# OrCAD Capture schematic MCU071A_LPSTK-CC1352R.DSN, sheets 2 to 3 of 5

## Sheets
2 2_Peripherals: size A3
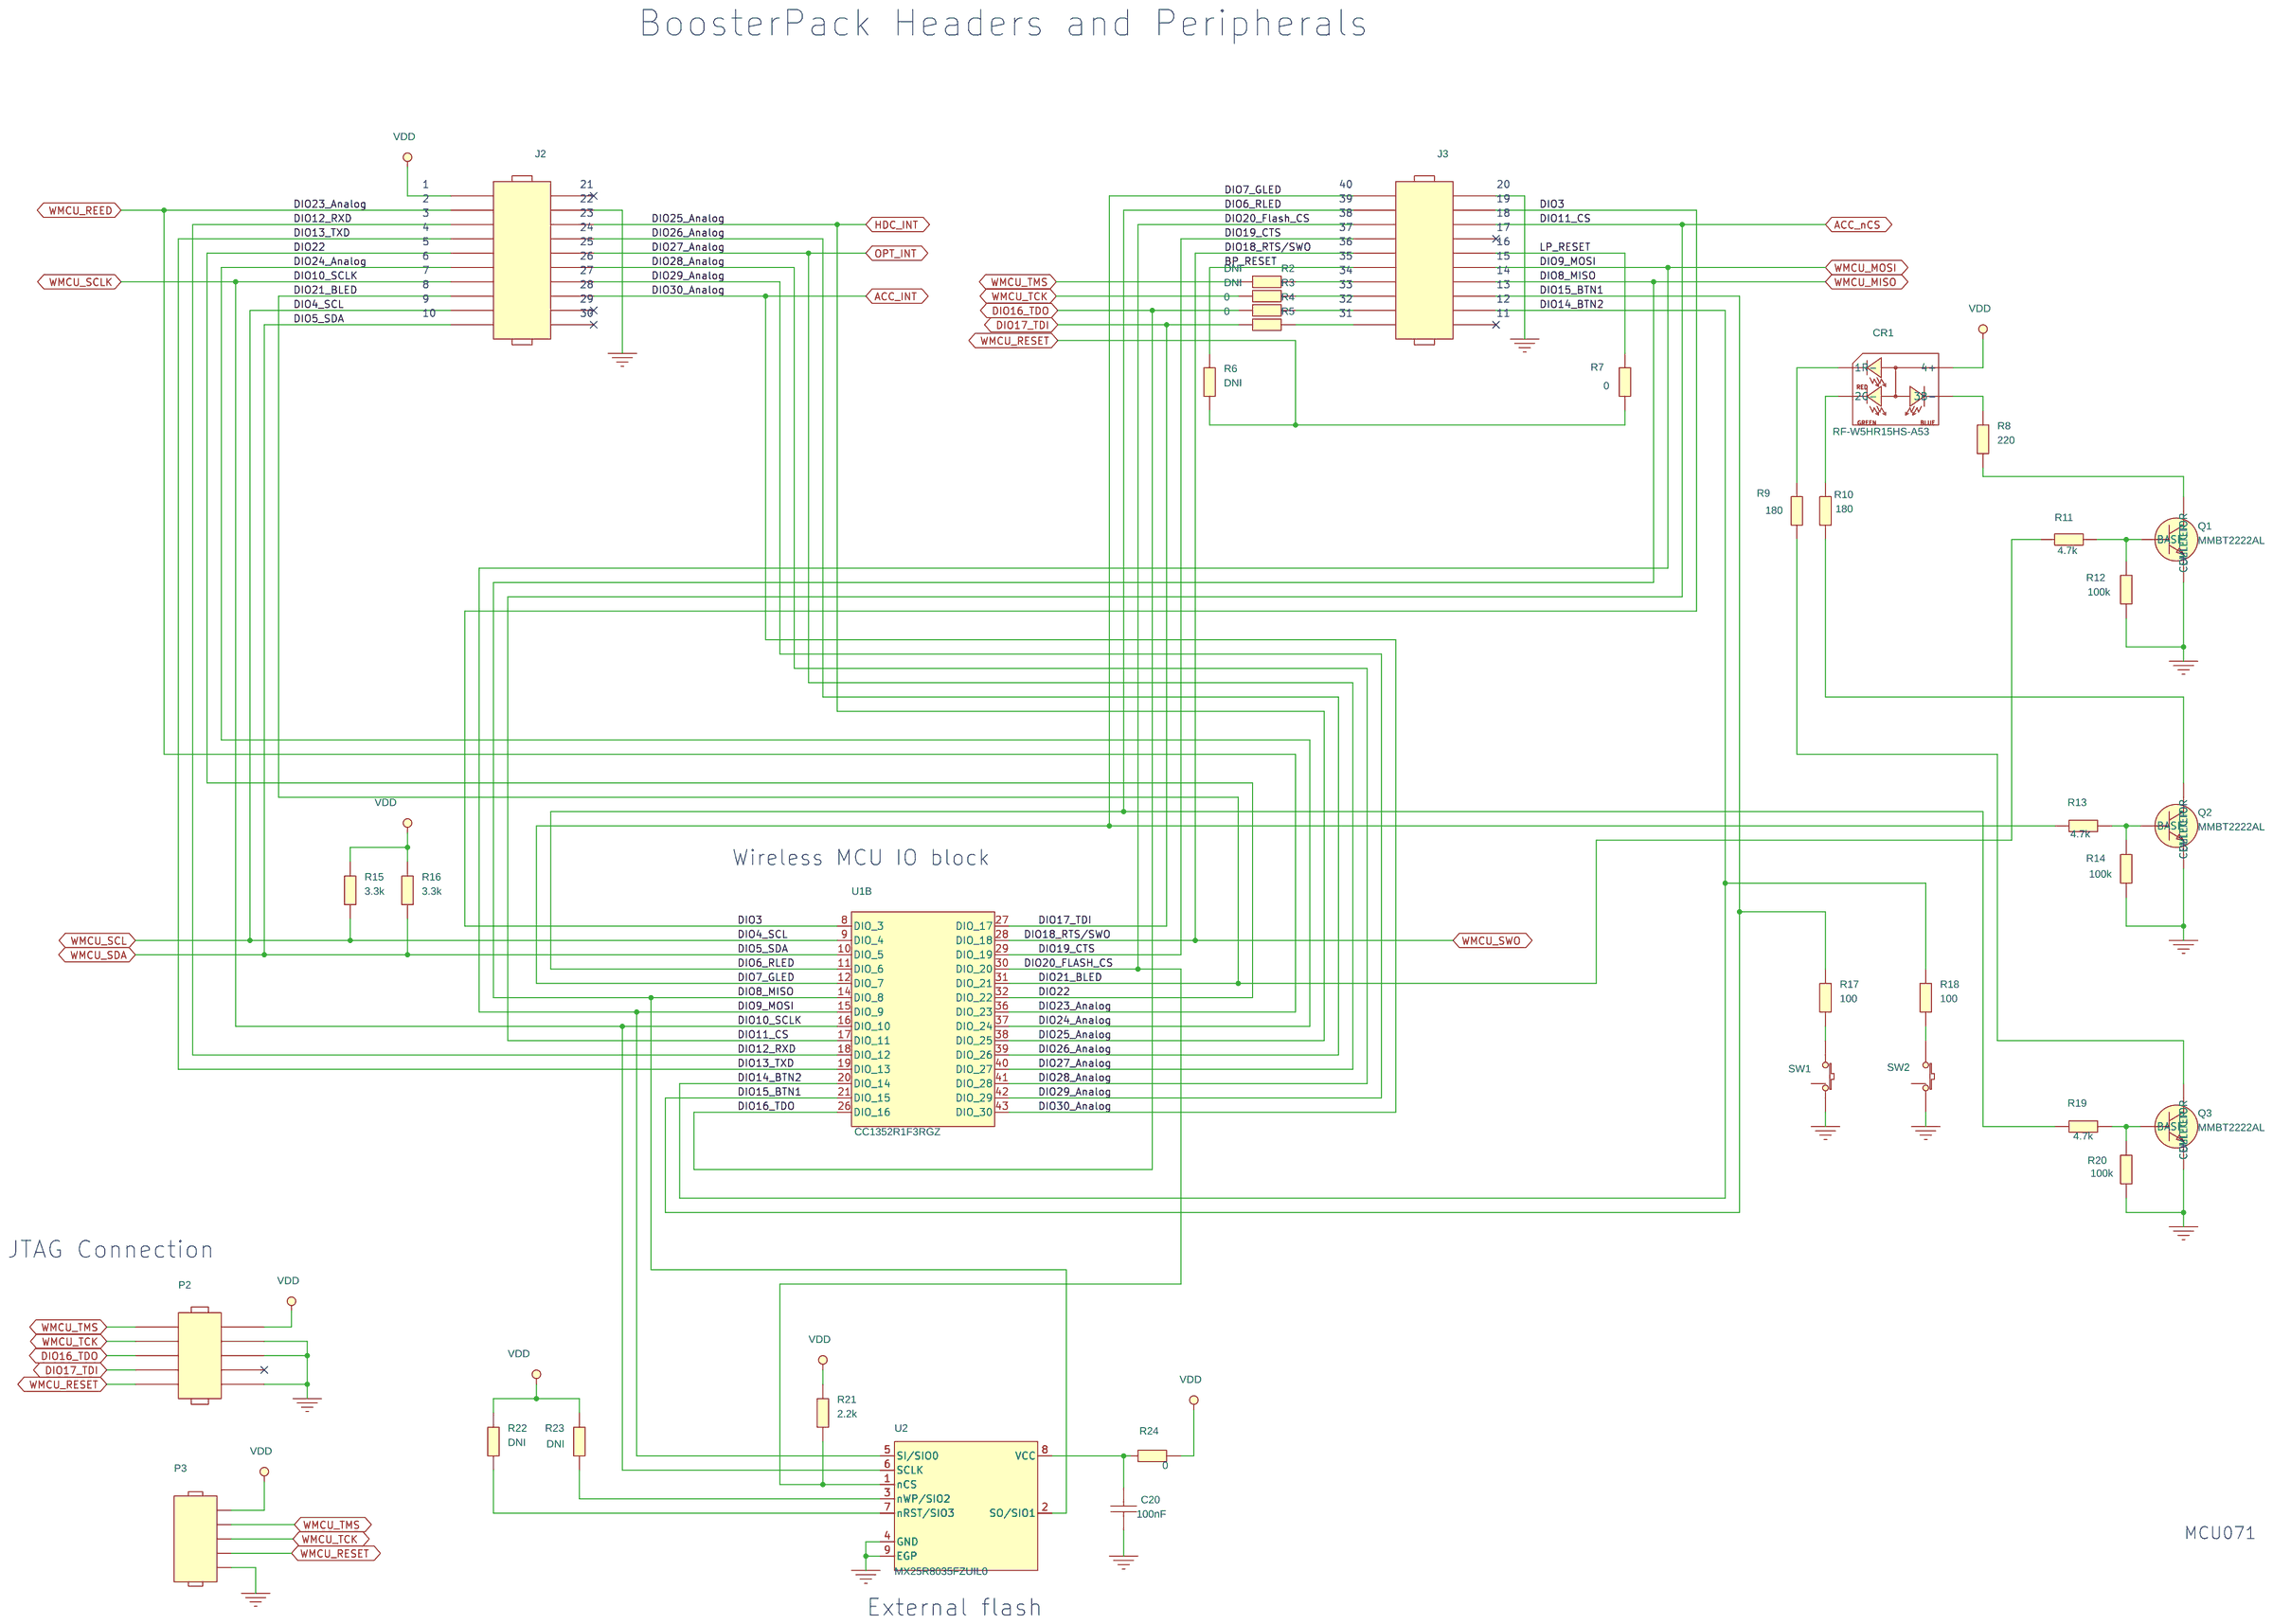
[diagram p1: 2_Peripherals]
3 3_Sensors: size A3; title: LPSTK- CC1352R1
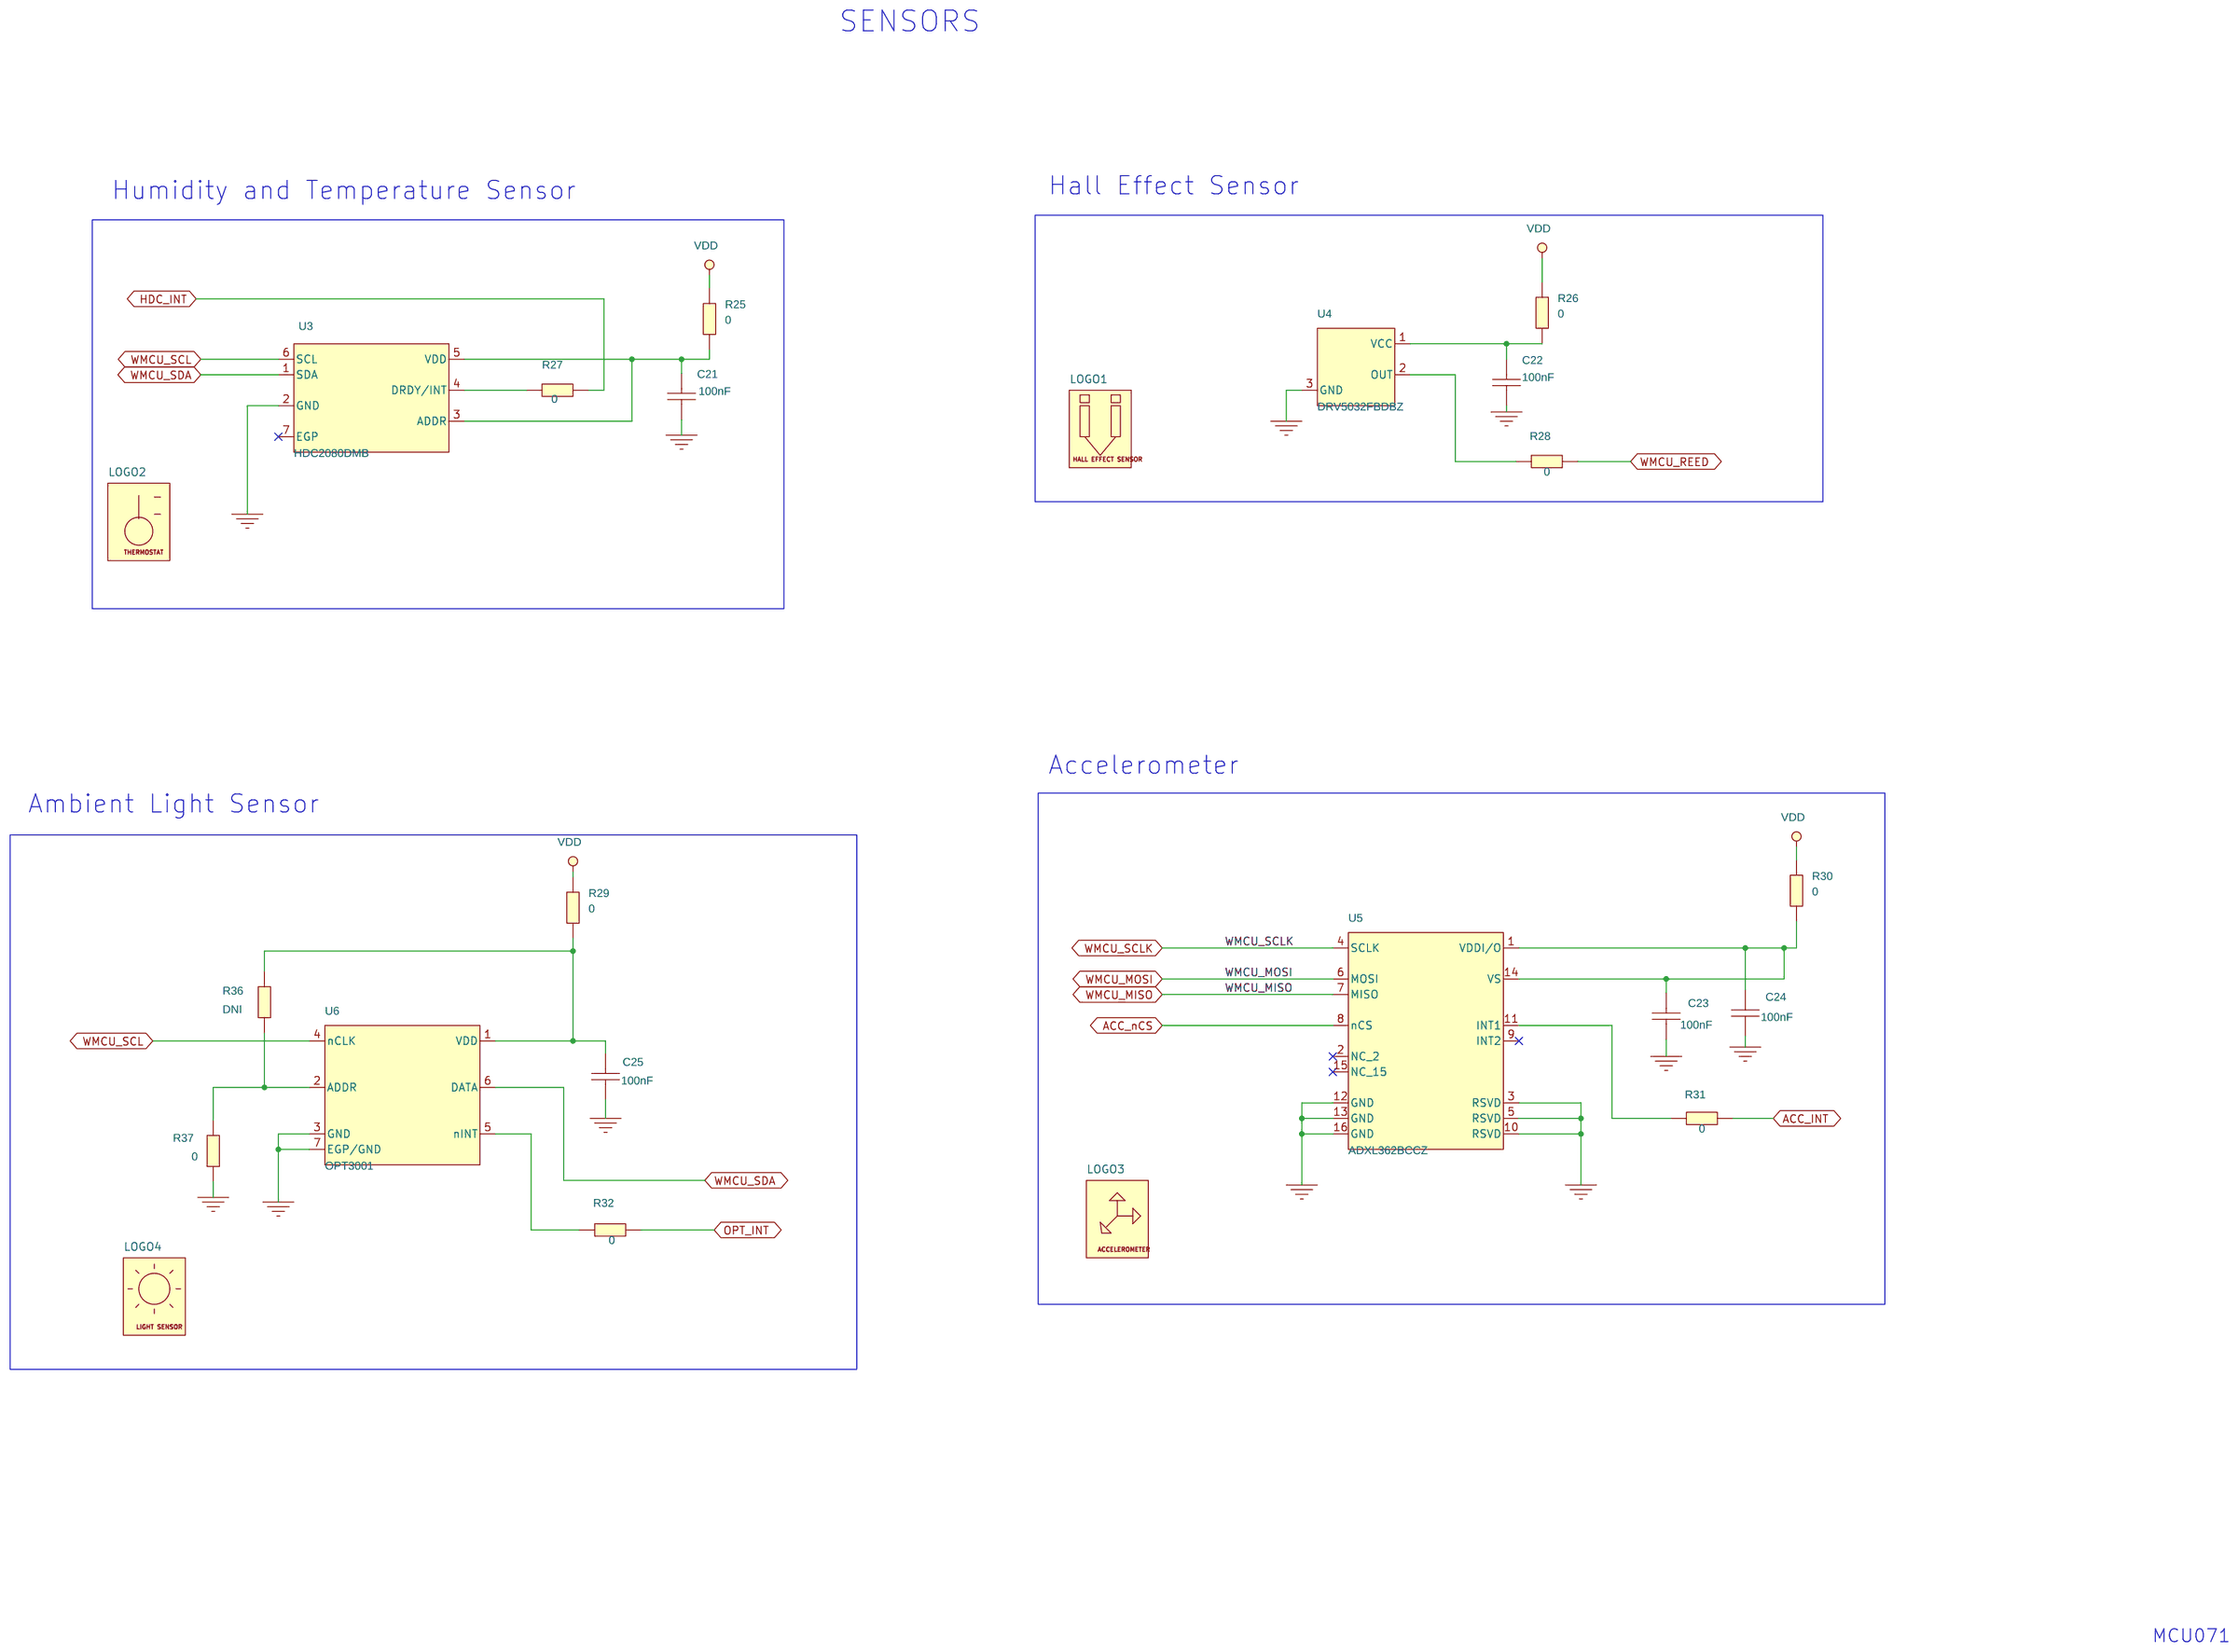
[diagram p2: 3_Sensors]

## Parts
sheet 1_RF
U1  CC1352R1F3RGZ  [QFNFC50P700X700X100-49A2N]  (sections A,B)
sheet 2_Peripherals
C20  100nF  [CAPC1005X60A2N]
CR1  RF-W5HR15HS-A53  [LED_RFW5HR15HSA53_A2N]
J2  313220S1411  [HARWIN_M209761046B]
J3  313220S1411  [HARWIN_M209761046B]
P2  FTSH-105-01-F-DV-K  [SAMTEC_FTSH10501FDVK_A2N]
P3  DNI  [HARWIN_M52040023V0545_A2B]
Q1  MMBT2222AL  [SOT95P237X111-3A2N]
Q2  MMBT2222AL  [SOT95P237X111-3A2N]
Q3  MMBT2222AL  [SOT95P237X111-3A2N]
R2  DNI  [RESC0603X35B2N]
R3  DNI  [RESC0603X35B2N]
R4  0  [RESC0603X35B2N]
R5  0  [RESC0603X35B2N]
R6  DNI  [RESC1005X40B2N]
R7  0  [RESC1005X40A2N]
R8  220  [RESC1005X40B2N]
R9  180  [RESC1005X40B2N]
R10  180  [RESC1005X40B2N]
R11  4.7k  [RESC0603X35B2N]
R12  100k  [RESC0603X35B2N]
R13  4.7k  [RESC0603X35B2N]
R14  100k  [RESC0603X35B2N]
R15  3.3k  [RESC1005X40B2N]
R16  3.3k  [RESC1005X40B2N]
R17  100  [RESC1005X40B2N]
R18  100  [RESC1005X40B2N]
R19  4.7k  [RESC0603X35B2N]
R20  100k  [RESC0603X35B2N]
R21  2.2k  [RESC1005X40B2N]
R22  DNI  [RESC1005X40B2N]
R23  DNI  [RESC1005X40B2N]
R24  0  [RESC0603X35B2N]
SW1  MTA2-WNC  [SW_MTA2CN]
SW2  MTA2-WNC  [SW_MTA2CN]
U2  MX25R8035FZUIL0  [SON50P300X200X60-9B2N]
sheet 3_Sensors
C21  100nF  [CAPC1005X60A2N]
C22  100nF  [CAPC1005X60A2N]
C23  100nF  [CAPC1005X60A2N]
C24  100nF  [CAPC1005X60A2N]
C25  100nF  [CAPC1005X60A2N]
LOGO1  Logo_HALL_EFFECT_SENSOR  [LABEL_HALL_EFFECT_SENSOR_TI]
LOGO2  Logo_THERMOSTAT  [LABEL_THERMOSTAT_TI]
LOGO3  Logo_ACCELEROMETER  [LABEL_ACCELEROMETER_TI]
LOGO4  Logo_LIGHT_SENSOR  [LABEL_LIGHT_SENSOR_TI]
R25  0  [RESC0603X35B2N]
R26  0  [RESC0603X35B2N]
R27  0  [RESC0603X35B2N]
R28  0  [RESC0603X35B2N]
R29  0  [RESC0603X35B2N]
R30  0  [RESC0603X35B2N]
R31  0  [RESC0603X35B2N]
R32  0  [RESC0603X35B2N]
R36  DNI  [RESC0603X35B2N]
R37  0  [RESC0603X35B2N]
U3  HDC2080DMB  [SON100P300X300X80-7B2N]
U4  DRV5032FBDBZ  [SOT95P237X112-3A2N]
U5  ADXL362BCCZ  [LGAFC16S50P300X325X114]
U6  OPT3001  [SON65P200X200X65-7N]

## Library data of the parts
U1 = IC_RF_CC1352_QFN48_V1: IC, CUSTOM, CC1352R1F3RGZ, QFN48-EP, SMD; ALT_SYMBOLS: QFNFC50P700X700X100-49A2L,QFNFC50P700X700X100-49A2M; Additional Datasheet URL: http://www.ti.com/lit/ml/mpqf123f/mpqf123f.pdf; Datasheet URL: http://www.ti.com/lit/ds/symlink/cc1352r.pdf; Exclusive for Customers: TEXAS INSTRUMENTS NORWAY; Mass: N/A; Maximum Operating Temperature: N/A; Minimum Operating Temperature: N/A; Mounting Type: SMD; NOTEfied URL: https://notefied-dynamic-precision.com/NOTEfiedWebInterface/part/show?partNumber=18-33499; Notes: Custom item: preliminary.; PCB Package: QFN48-EP; Packing Size: 250; Packing Type: Missing Info; Part Number: 18-33499; Part Type: IC|DIGITAL|WIRELESS|OTHER; REACH/SVHC Compliance: Missing Info; REACH/SVHC Details: N/A; REACH/SVHC Source: N/A; REACH/SVHC Status: Missing Info; ROHS: Missing Info; Rated Voltage: N/A; Revision: R019; Status: Released; Texas Part Status: Under Review; Type: IC; Vendor: TEXAS INSTRUMENTS; Vendor Part Number: CC1352R1F3RGZT; Vendor Part Status: Preliminary
C20-C25 = CAPACITOR: CAPACITOR, CERAMIC X5R, 100nF, 10V, -10%+/10%, -55DEGC /+85DEGC, 0402, SMD; ALT_SYMBOLS: CAPC1005X60A2L,CAPC1005X60A2M; Additional Datasheet URL: http://www.avx.com/products/ceramic-capacitors/surface-mount/x5r-dielectric/; Budgetary Price: 0.004 EUR; Country of Origin: China,Czech Republic,El Salvador,Japan,Malaysia,United Kingdom; Datasheet URL: http://datasheets.avx.com/cx5r.pdf; Dielectric Type: X5R; Lead Time: 11; Mass: 0.001g; Maximum Operating Temperature: +85DEGC; Maximum Tolerance: +10%; Minimum Operating Temperature: -55DEGC; Minimum Tolerance: -10%; Mounting Type: SMD; NOTEfied URL: https://notefied-dynamic-precision.com/NOTEfiedWebInterface/part/show?partNumber=02-04065; PCB Package: 0402; Packing Size: 10000; Packing Type: Tape & Reel; Part Number: 02-04065; Part Type: Capacitor|CERAMIC|0402|STANDARD; ROHS: Compliant; Rated Voltage: 10V; Revision: R008; Status: Released; Type: Capacitor; Vendor: AVX; Vendor Part Number: 0402ZD104KAT2A; Vendor Part Status: Active
CR1 = LED_RGB_V1_0: OPTO, LED, RGB, 618nm TO 628nm/525nm TO 535nm/460nm TO 470nm, 1.6V TO 2.3V/2.4V TO 3.1V/2.4V TO 3.1V, 0.008A/0.005A/0.003A, 0.046W/0.047W/0.047W, SMD; ALT_SYMBOLS: LED_RFW5HR15HSA53_A2L,LED_RFW5HR15HSA53_A2M; Additional Datasheet URL: N/A; Datasheet URL: http://www.refond.com; Mass: N/A; Maximum Operating Temperature: +85DEGC; Minimum Operating Temperature: -30DEGC; Mounting Type: SMD; NOTEfied URL: https://notefied-dynamic-precision.com/NOTEfiedWebInterface/part/show?partNumber=15-03036; Packing Size: 15000; Packing Type: Tape & Reel; Part Number: 15-03036; Part Type: Opto|LED|OTHER SMD; REACH/SVHC Compliance: Missing Info; REACH/SVHC Details: N/A; REACH/SVHC Source: N/A; REACH/SVHC Status: Missing Info; ROHS: Compliant; Rated Current: 0.008A / 0.005A / 0.003A; Rated Power: 0.046W / 0.047W / 0.047W; Rated Voltage: 1.6V TO 2.3V / 2.4V TO 3.1V / 2.4V TO 3.1V; Revision: R001; Status: Released; Texas Part Status: Under Review; Type: Opto; Vendor: REFOND; Vendor Part Status: Active
J2 J3 = CONN_HEADER_2X10_P: CONNECTOR, HEADER, MALE, STRAIGHT, 2 ROWS, 20 PINS, PITCH 2.54mm, PTH; ALT_SYMBOLS: HARWIN_M209761046C,HARWIN_M209761046A; Additional Datasheet URL: https://cdn.harwin.com/pdfs/M20-976.pdf; Budgetary Price: 0.32175 USD; CLASS: IO; Country of Origin: United States,United Kingdom,Singapore; Datasheet URL: https://cdn.harwin.com/pdfs/C001XX_M20_Series_Connectors.pdf; Lead Time: 7; Mass: 1.056g; Maximum Operating Temperature: +105DEGC; Minimum Operating Temperature: -40DEGC; Mounting Type: PTH; NOTEfied URL: https://notefied-dynamic-precision.com/NOTEfiedWebInterface/part/show?partNumber=06-00136; Number of Positions: 20; Number of Rows: 2; Packing Size: 300; Packing Type: Bulk; Part Number: 06-00136; Part Type: Connector|HEADER|STANDARD; Pitch: 2.54mm; ROHS: Compliant; Rated Current: 3A; Revision: R009; Status: Released; Type: Connector; Vendor: LYCONN; Vendor Part Status: Active
P2 = CONN_HEADER_2X5: CONNECTOR, HEADER, MALE, STRAIGHT, 2 ROWS, 10 PINS, PITCH 1.27mm, SMD; ALT_SYMBOLS: SAMTEC_FTSH10501FDVK_A2L,SAMTEC_FTSH10501FDVK_A2M; Additional Datasheet URL: http://suddendocs.samtec.com/prints/ftsh-1xx-xx-xxx-dv-xxx-xxx-mkt.pdf; Budgetary Price: 1.682 USD; CLASS: IO; Country of Origin: China,Costa Rica,Malaysia,Singapore,United States; Datasheet URL: http://suddendocs.samtec.com/catalog_english/ftsh_smt.pdf; FPLIST: SAMTEC_FTSH10501FDVK_A2N,SAMTEC_FTSH-105-01-F-DV-K-10N; Lead Time: 3; Mass: 0.31701g; Maximum Operating Temperature: +125DEGC; Minimum Operating Temperature: -55DEGC; Mounting Type: SMD; NOTEfied URL: https://notefied-dynamic-precision.com/NOTEfiedWebInterface/part/show?partNumber=06-00166; Number of Positions: 10; Number of Rows: 2; Packing Size: 92; Packing Type: Tube; Part Number: 06-00166; Part Type: Connector|HEADER|STANDARD; Pitch: 1.27mm; REACH/SVHC Compliance: Compliant; REACH/SVHC Details: SVHC List Version Jun 20, 2016; REACH/SVHC Source: Material Declaration; REACH/SVHC Status: Unaffected; ROHS: Compliant; Rated Current: 1.75A; Revision: R017; Status: Released; Texas Part Status: Under Review; Type: Connector; Vendor: SAMTEC; Vendor Part Status: Active
P3 = CONN_HEADER_5_P_S: CONNECTOR, HEADER, MALE, STRAIGHT, 1 ROW, 5 PINS, PITCH 1.27mm, PTH; Additional Datasheet URL: https://cdn.harwin.com/pdfs/M52-040023VXX45.pdf; Budgetary Price: 0.36465 USD; Country of Origin: Taiwan; Datasheet URL: https://cdn.harwin.com/pdfs/C029XX_M50_and_M52_Series_Connectors.pdf; Lead Time: 7; Mass: 0.135g; Maximum Operating Temperature: +105DEGC; Minimum Operating Temperature: -40DEGC; Mounting Type: PTH; NOTEfied URL: https://notefied-dynamic-precision.com/NOTEfiedWebInterface/part/show?partNumber=06-04967; Number of Positions: 5; Number of Rows: 1; Packing Size: 1000; Packing Type: Bulk; Part Number: 06-04967; Part Type: Connector|HEADER|STANDARD; Pitch: 1.27mm; ROHS: Compliant; Rated Current: 1A; Revision: R012; Status: Released; Texas Part Status: Under Review; Type: Connector; Vendor: HARWIN; Vendor Part Number: M52-040023V0545; Vendor Part Status: Active
Q1-Q3 = NPN_BEC: TRANSISTOR, BIPOLAR, NPN, 40V, 0.6A, 0.225W, SOT23-3, SMD; ALT_SYMBOLS: SOT95P237X111-3A2L,SOT95P237X111-3A2M; Additional Datasheet URL: http://www.onsemi.com/pub/Collateral/318-08.PDF; Budgetary Price: 0.0123 USD; Country of Origin: China; Datasheet URL: http://www.onsemi.com/pub/Collateral/MMBT2222LT1-D.PDF; Lead Time: 4; Mass: 0.00802g; Maximum Operating Temperature: +150DEGC; Minimum Operating Temperature: -55DEGC; Mounting Type: SMD; NOTEfied URL: https://notefied-dynamic-precision.com/NOTEfiedWebInterface/part/show?partNumber=16-00819; PCB Package: SOT23-3; Packing Size: 3000; Packing Type: Tape & Reel; Part Number: 16-00819; Part Type: Transistor|BIPOLAR|NPN; ROHS: Compliant; Rated Current: 0.6A; Rated Power: 0.225W; Rated Voltage: 40V; Revision: R023; Status: Released; Type: Transistor; Vendor: ON SEMICONDUCTOR; Vendor Part Number: MMBT2222ALT1G; Vendor Part Status: Active
R2 R3 R36 = RESISTOR: RESISTOR, TBD, 0201, SMD, DNM; ALT_SYMBOLS: RESC0603X35B2L,RESC0603X35B2M; Additional Datasheet URL: N/A; Country of Origin: Missing Info; Datasheet URL: N/A; Maximum Operating Temperature: N/A; Maximum Temperature Coefficient: N/A; Maximum Tolerance: N/A; Minimum Operating Temperature: N/A; Minimum Temperature Coeficient: N/A; Minimum Tolerance: N/A; Mounting Type: SMD; NOTEfied URL: https://notefied-dynamic-precision.com/NOTEfiedWebInterface/part/show?partNumber=01-02470; PCB Package: 0201; Part Number: 01-02470; Part Type: Resistor|0201|STANDARD; ROHS: Compliant; Rated Current: N/A; Rated Power: N/A; Rated Voltage: N/A; Resistance: N/A; Revision: R014; Status: Released; Texas Part Status: Under Review; Type: Resistor; Vendor: MANUFACTURER SELECTION; Vendor Part Number: RESISTOR_TBD_0201_DNM; Vendor Part Status: Active
R4 R5 R24-R32 R37 = RESISTOR: RESISTOR, THICK FILM, 0, 0.05W, 30V, -55DEGC/+155DEGC, 0201, SMD; ALT_SYMBOLS: RESC0603X35B2L,RESC0603X35B2M; Additional Datasheet URL: N/A; Budgetary Price: 0.0243 USD; Country of Origin: Missing Info; Datasheet URL: N/A; Mass: N/A; Maximum Operating Temperature: +155DEGC; Maximum Temperature Coefficient: +100PPM/DEGC; Maximum Tolerance: N/A; Minimum Operating Temperature: -55DEGC; Minimum Temperature Coeficient: -100PPM/DEGC; Minimum Tolerance: N/A; Mounting Type: SMD; NOTEfied URL: https://notefied-dynamic-precision.com/NOTEfiedWebInterface/part/show?partNumber=01-02467; PCB Package: 0201; Packing Size: 5000; Packing Type: Tape & Reel; Part Number: 01-02467; Part Type: Resistor|0201|JUMPER; ROHS: Compliant; Rated Current: N/A; Rated Power: 0.05W; Rated Voltage: 30V; Resistor Type: THICK FILM; Revision: R011; Status: Released; Type: Resistor; Vendor: Yageo; Vendor Part Number: RC0201FR-070RL; Vendor Part Status: Active
R6 R22 R23 = RESISTOR: RESISTOR, TBD, 0402, SMD, DNM; Additional Datasheet URL: N/A; AutoDoc File: https://notefied-dynamic-precision.com/DB/Apps/Desktop/Item/Object.aspx?id=113312; BU Name: TEXAS INSTRUMENTS NORWAY; Budget Currency: N/A; Budget Price: N/A; Country of Origin: Missing Info; Datasheet URL: N/A; Datasheet URL 1: N/A; Datasheet URL 2: N/A; Esd Level: N/A; Exclusive for Customers: TEXAS INSTRUMENTS NORWAY; LifeCycle Status: ACTIVE; MPN: DNM; MPN Status: ACTIVE; MSL: N/A; MTBF: N/A; MTBF Standard: N/A; Manufacturer: DO NOT MOUNT; Max Oper Temp: N/A; Max TC: N/A; Max Tol: N/A; Maximum Operating Temperature: N/A; Maximum Temperature Coefficient: N/A; Maximum Tolerance: N/A; Min Oper Temp: N/A; Min TC: N/A; Min Tol: N/A; Minimum Operating Temperature: N/A; Minimum Temperature Coeficient: N/A; Minimum Tolerance: N/A; Mounting Type: SMD; NOTE Status: PREFERRED; NOTEfied URL: https://notefied-dynamic-precision.com/NOTEfiedWebInterface/part/show?partNumber=01-22339; Notes: Standard item: Duplicate Reason: custom footprint for TEXAS INSTRUMENTS NORWAY.; Old Footprint: RESC1005X40N,0402; PCB Package: 0402; Part Number: 01-22339; Part Type: Resistor|0402|STANDARD; ROHS: Compliant; Rated Current: N/A; Rated Power: N/A; Rated Voltage: N/A; Resistance: N/A; Resistor Type: THICK FILM; Revision: R012; RoHS Status: MISSING_INFO; Rtd Current: N/A; Rtd Power: N/A; Rtd Voltage: N/A; Status: Released; Texas Part Status: Under Review; Type: Resistor; Vendor: MANUFACTURER SELECTION; Vendor Part Number: RESISTOR_TBD_0402_DNM; Vendor Part Status: Active; WEIGHT: N/A
R7 = RESISTOR: RESISTOR, THICK FILM, 0, 0.063W, 50V, -55DEGC/+155DEGC, 0402, SMD; ALT_SYMBOLS: RESC1005X40A2L,RESC1005X40A2M; Additional Datasheet URL: N/A; Budgetary Price: 0.00244 USD; Country of Origin: Missing Info; Datasheet URL: N/A; Mass: N/A; Maximum Operating Temperature: +155DEGC; Maximum Temperature Coefficient: +200PPM/DEGC; Maximum Tolerance: N/A; Minimum Operating Temperature: -55DEGC; Minimum Temperature Coeficient: -200PPM/DEGC; Minimum Tolerance: N/A; Mounting Type: SMD; NOTEfied URL: https://notefied-dynamic-precision.com/NOTEfiedWebInterface/part/show?partNumber=01-11587; PCB Package: 0402; Packing Size: 10000; Packing Type: Tape & Reel; Part Number: 01-11587; Part Type: Resistor|0402|JUMPER; ROHS: Compliant; Rated Current: N/A; Rated Power: 0.063W; Rated Voltage: 50V; Resistor Type: THICK FILM; Revision: R014; Status: Released; Type: Resistor; Vendor: Yageo; Vendor Part Number: RC0402JR-070RL; Vendor Part Status: Active
R8 = RESISTOR: RESISTOR, THICK FILM, 220, -5%/+5%, 0.063W, 50V, -55DEGC/+155DEGC, 0402, SMD; Additional Datasheet URL: N/A; AutoDoc File: https://notefied-dynamic-precision.com/DB/Apps/Desktop/Item/Object.aspx?id=113319; BU Name: TEXAS INSTRUMENTS NORWAY; Budget Currency: EUR; Budget Price: 0.014; Budgetary Price: 0.014 EUR; Client Status: UNDER_REVIEW; Country of Origin: Israel; Datasheet URL: http://www.vishay.com/docs/20035/dcrcwe3.pdf; Datasheet URL 1: http://www.vishay.com/docs/20035/dcrcwe3.pdf; Datasheet URL 2: N/A; Definied Quality: INDUSTRIAL; Esd Level: N/A; Exclusive for Customers: TEXAS INSTRUMENTS NORWAY; Lead Time: 18; LifeCycle Status: ACTIVE; MPN: RESISTOR_0402_220_+/-5%_50V_0.063W_M_+/-200ppm; MPN Status: ACTIVE; MSL: N/A; MTBF: N/A; MTBF Standard: N/A; Manufacturer: MANUFACTURER SELECTION; Mass: 0.00065g; Max Oper Temp: +155DEGC; Max TC: +200PPM/DEGC; Max Tol: +5%; Maximum Operating Temperature: +155DEGC; Maximum Temperature Coefficient: +200PPM/DEGC; Maximum Tolerance: +5%; Min Oper Temp: -55DEGC; Min TC: -200PPM/DEGC; Min Tol: -5%; Minimum Operating Temperature: -55DEGC; Minimum Temperature Coeficient: -200PPM/DEGC; Minimum Tolerance: -5%; Mounting Type: SMD; NOTE Status: PREFERRED; NOTEfied URL: https://notefied-dynamic-precision.com/NOTEfiedWebInterface/part/show?partNumber=01-22346; Notes: Standard item: Duplicate Reason: custom footprint for TEXAS INSTRUMENTS NORWAY.; Old Footprint: RESC1005X40N; PCB Package: 0402; Packing Size: 10000; Packing Type: Tape & Reel; Part Number: 01-22346; Part Type: Resistor|0402|STANDARD; REACH/SVHC Compliance: Compliant; REACH/SVHC Details: SVHC List Version Jun 20, 2016; REACH/SVHC Source: Material Declaration; REACH/SVHC Status: Unaffected; REACH/SVHC_COMPLIANCE: COMPLIANT; REACH/SVHC_DETAILS: SVHC LIST VERSION Jun 20, 2016; REACH/SVHC_SOURCE: MATERIAL DECLARATION; REACH/SVHC_STATUS: UNAFFECTED; ROHS: Exempt; Rated Current: N/A; Rated Power: 0.063W; Rated Voltage: 50V; Resistor Type: THICK FILM; Revision: R013; RoHS Status: ROHS_COMPLIANT_WITH_EXEMPTION; Rtd Current: N/A; Rtd Power: 0.063W; Rtd Voltage: 50V; Status: Released; Texas Part Status: Under Review; Type: Resistor; Vendor: VISHAY; Vendor Part Number: CRCW0402220RJNED; Vendor Part Status: Active; WEIGHT: 0.00065g
R9 R10 = RESISTOR: RESISTOR, THICK FILM, 180, -5%/+5%, 0.063W, 50V, -55DEGC/+155DEGC, 0402, SMD; Additional Datasheet URL: N/A; AutoDoc File: https://notefied-dynamic-precision.com/DB/Apps/Desktop/Item/Object.aspx?id=113318; BU Name: TEXAS INSTRUMENTS NORWAY; Budget Currency: EUR; Budget Price: 0.014; Budgetary Price: 0.014 EUR; Client Status: UNDER_REVIEW; Country of Origin: Missing Info; Datasheet URL: http://www.vishay.com/docs/20035/dcrcwe3.pdf; Datasheet URL 1: http://www.vishay.com/docs/20035/dcrcwe3.pdf; Datasheet URL 2: N/A; Definied Quality: INDUSTRIAL; Esd Level: N/A; Exclusive for Customers: TEXAS INSTRUMENTS NORWAY; Lead Time: 18; LifeCycle Status: ACTIVE; MPN: RESISTOR_0402_180_+/-5%_50V_0.063W_M_+/-200ppm; MPN Status: ACTIVE; MSL: N/A; MTBF: N/A; MTBF Standard: N/A; Manufacturer: MANUFACTURER SELECTION; Mass: 0.00065g; Max Oper Temp: +155DEGC; Max TC: +200PPM/DEGC; Max Tol: +5%; Maximum Operating Temperature: +155DEGC; Maximum Temperature Coefficient: +200PPM/DEGC; Maximum Tolerance: +5%; Min Oper Temp: -55DEGC; Min TC: -200PPM/DEGC; Min Tol: -5%; Minimum Operating Temperature: -55DEGC; Minimum Temperature Coeficient: -200PPM/DEGC; Minimum Tolerance: -5%; Mounting Type: SMD; NOTE Status: PREFERRED; NOTEfied URL: https://notefied-dynamic-precision.com/NOTEfiedWebInterface/part/show?partNumber=01-22345; Notes: Standard item: Duplicate Reason: custom footprint for TEXAS INSTRUMENTS NORWAY.; Old Footprint: RESC1005X40N; PCB Package: 0402; Packing Size: 10000; Packing Type: Tape & Reel; Part Number: 01-22345; Part Type: Resistor|0402|STANDARD; REACH/SVHC Compliance: Compliant; REACH/SVHC Details: SVHC List Version Jun 20, 2016; REACH/SVHC Source: Material Declaration; REACH/SVHC Status: Unaffected; REACH/SVHC_COMPLIANCE: COMPLIANT; REACH/SVHC_DETAILS: SVHC LIST VERSION Jun 20, 2016; REACH/SVHC_SOURCE: MATERIAL DECLARATION; REACH/SVHC_STATUS: UNAFFECTED; ROHS: Exempt; Rated Current: N/A; Rated Power: 0.063W; Rated Voltage: 50V; Resistor Type: THICK FILM; Revision: R013; RoHS Status: ROHS_COMPLIANT_WITH_EXEMPTION; Rtd Current: N/A; Rtd Power: 0.063W; Rtd Voltage: 50V; Status: Released; Texas Part Status: Under Review; Type: Resistor; Vendor: VISHAY; Vendor Part Number: CRCW0402180RJNED; Vendor Part Status: Active; WEIGHT: 0.00065g
R11 R13 R19 = RESISTOR: RESISTOR, THICK FILM, 4.7k, -5%/+5%, 0.05W, 30V, -55DEGC/+155DEGC, 0201, SMD; ALT_SYMBOLS: RESC0603X35B2L,RESC0603X35B2M; Additional Datasheet URL: N/A; Budgetary Price: 0.0041 USD; Country of Origin: Taiwan; Datasheet URL: http://www.vishay.com/docs/20052/crcw0201e3.pdf; Lead Time: 7; Mass: 0.00017g; Maximum Operating Temperature: +155DEGC; Maximum Temperature Coefficient: +200PPM/DEGC; Maximum Tolerance: +5%; Minimum Operating Temperature: -55DEGC; Minimum Temperature Coeficient: -200PPM/DEGC; Minimum Tolerance: -5%; Mounting Type: SMD; NOTEfied URL: https://notefied-dynamic-precision.com/NOTEfiedWebInterface/part/show?partNumber=01-04188; PCB Package: 0201; Packing Size: 10000; Packing Type: Tape & Reel; Part Number: 01-04188; Part Type: Resistor|0201|STANDARD; ROHS: Exempt; Rated Current: N/A; Rated Power: 0.05W; Rated Voltage: 30V; Resistor Type: THICK FILM; Revision: R005; Status: Released; Type: Resistor; Vendor: VISHAY; Vendor Part Number: CRCW02014K70JNED; Vendor Part Status: Active
R12 R14 R20 = RESISTOR: RESISTOR, THICK FILM, 100k, -5%/+5%, 0.05W, 25V, -55DEGC/+125DEGC, 0201, SMD; ALT_SYMBOLS: RESC0603X35B2L,RESC0603X35B2M; Additional Datasheet URL: N/A; Budgetary Price: 0.00218 USD; Country of Origin: China,Japan,Taiwan; Datasheet URL: https://www.seielect.com/Catalog/SEI-RMCF_RMCP.pdf; Lead Time: 22; Mass: 0.0001509g; Maximum Operating Temperature: +125DEGC; Maximum Temperature Coefficient: +200PPM/DEGC; Maximum Tolerance: +5%; Minimum Operating Temperature: -55DEGC; Minimum Temperature Coeficient: -200PPM/DEGC; Minimum Tolerance: -5%; Mounting Type: SMD; NOTEfied URL: https://notefied-dynamic-precision.com/NOTEfiedWebInterface/part/show?partNumber=01-00530; PCB Package: 0201; Packing Size: 10000; Packing Type: Tape & Reel; Part Number: 01-00530; Part Type: Resistor|0201|STANDARD; ROHS: Exempt; Rated Current: N/A; Rated Power: 0.05W; Rated Voltage: 25V; Resistor Type: THICK FILM; Revision: R007; Status: Released; Type: Resistor; Vendor: SEI STACKPOLE; Vendor Part Number: RMCF0201JT100K; Vendor Part Status: Active
R15 R16 = RESISTOR: RESISTOR, THICK FILM, 3.3k, -5%/+5%, 0.063W, 50V, -55DEGC/+155DEGC, 0402, SMD; Additional Datasheet URL: N/A; AutoDoc File: https://notefied-dynamic-precision.com/DB/Apps/Desktop/Item/Object.aspx?id=114561; BU Name: TEXAS INSTRUMENTS NORWAY; Budget Currency: EUR; Budget Price: 0.014; Budgetary Price: 0.014 EUR; Client Status: UNDER_REVIEW; Country of Origin: Israel; Datasheet URL: http://www.vishay.com/docs/20035/dcrcwe3.pdf; Datasheet URL 1: http://www.vishay.com/docs/20035/dcrcwe3.pdf; Datasheet URL 2: N/A; Definied Quality: INDUSTRIAL; Esd Level: N/A; Exclusive for Customers: TEXAS INSTRUMENTS NORWAY; Lead Time: 18; LifeCycle Status: ACTIVE; MPN: RESISTOR_0402_3.3k_+/-5%_50V_0.063W_M_+/-200ppm; MPN Status: ACTIVE; MSL: N/A; MTBF: N/A; MTBF Standard: N/A; Manufacturer: MANUFACTURER SELECTION; Mass: 0.00065g; Max Oper Temp: +155DEGC; Max TC: +200PPM/DEGC; Max Tol: +5%; Maximum Operating Temperature: +155DEGC; Maximum Temperature Coefficient: +200PPM/DEGC; Maximum Tolerance: +5%; Min Oper Temp: -55DEGC; Min TC: -200PPM/DEGC; Min Tol: -5%; Minimum Operating Temperature: -55DEGC; Minimum Temperature Coeficient: -200PPM/DEGC; Minimum Tolerance: -5%; Mounting Type: SMD; NOTE Status: PREFERRED; NOTEfied URL: https://notefied-dynamic-precision.com/NOTEfiedWebInterface/part/show?partNumber=01-22488; Notes: Standard item: Duplicate Reason: custom footprint for TEXAS INSTRUMENTS NORWAY.; Old Footprint: RESC1005X40N; PCB Package: 0402; Packing Size: 10000; Packing Type: Tape & Reel; Part Number: 01-22488; Part Type: Resistor|0402|STANDARD; REACH/SVHC Compliance: Compliant; REACH/SVHC Details: SVHC List Version Jun 20, 2016; REACH/SVHC Source: Material Declaration; REACH/SVHC Status: Unaffected; REACH/SVHC_COMPLIANCE: COMPLIANT; REACH/SVHC_DETAILS: SVHC LIST VERSION Jun 20, 2016; REACH/SVHC_SOURCE: MATERIAL DECLARATION; REACH/SVHC_STATUS: UNAFFECTED; ROHS: Exempt; Rated Current: N/A; Rated Power: 0.063W; Rated Voltage: 50V; Resistor Type: THICK FILM; Revision: R013; RoHS Status: ROHS_COMPLIANT; Rtd Current: N/A; Rtd Power: 0.063W; Rtd Voltage: 50V; Status: Released; Texas Part Status: Under Review; Type: Resistor; Vendor: VISHAY; Vendor Part Number: CRCW04023K30JNED; Vendor Part Status: Active; WEIGHT: 0.00065g
R17 R18 = RESISTOR: RESISTOR, THICK FILM, 100, -5%/+5%, 0.063W, 50V, -55DEGC/+155DEGC, 0402, SMD; Additional Datasheet URL: N/A; AutoDoc File: https://notefied-dynamic-precision.com/DB/Apps/Desktop/Item/Object.aspx?id=114555; BU Name: TEXAS INSTRUMENTS NORWAY; Budget Currency: USD; Budget Price: 0.0014; Budgetary Price: 0.0014 USD; Client Status: UNDER_REVIEW; Country of Origin: United States; Datasheet URL: http://www.vishay.com/docs/20035/dcrcwe3.pdf; Datasheet URL 1: http://www.vishay.com/docs/20035/dcrcwe3.pdf; Datasheet URL 2: N/A; Definied Quality: INDUSTRIAL; Esd Level: N/A; Exclusive for Customers: TEXAS INSTRUMENTS NORWAY; Lead Time: 16; LifeCycle Status: ACTIVE; MPN: RESISTOR_0402_100_+/-5%_50V_0.063W_M_+/-200ppm; MPN Status: ACTIVE; MSL: N/A; MTBF: N/A; MTBF Standard: N/A; Manufacturer: MANUFACTURER SELECTION; Mass: 0.00065g; Max Oper Temp: +155DEGC; Max TC: +200PPM/DEGC; Max Tol: +5%; Maximum Operating Temperature: +155DEGC; Maximum Temperature Coefficient: +200PPM/DEGC; Maximum Tolerance: +5%; Min Oper Temp: -55DEGC; Min TC: -200PPM/DEGC; Min Tol: -5%; Minimum Operating Temperature: -55DEGC; Minimum Temperature Coeficient: -200PPM/DEGC; Minimum Tolerance: -5%; Mounting Type: SMD; NOTE Status: PREFERRED; NOTEfied URL: https://notefied-dynamic-precision.com/NOTEfiedWebInterface/part/show?partNumber=01-22482; Notes: Standard item: Duplicate Reason: custom footprint for TEXAS INSTRUMENTS NORWAY.; Old Footprint: RESC1005X40N; PCB Package: 0402; Packing Size: 10000; Packing Type: Tape & Reel; Part Number: 01-22482; Part Type: Resistor|0402|STANDARD; REACH/SVHC Compliance: Compliant; REACH/SVHC Details: SVHC List Version Jun 20, 2016; REACH/SVHC Source: Material Declaration; REACH/SVHC Status: Unaffected; REACH/SVHC_COMPLIANCE: COMPLIANT; REACH/SVHC_DETAILS: SVHC LIST VERSION Jun 20, 2016; REACH/SVHC_SOURCE: MATERIAL DECLARATION; REACH/SVHC_STATUS: UNAFFECTED; ROHS: Exempt; Rated Current: N/A; Rated Power: 0.063W; Rated Voltage: 50V; Resistor Type: THICK FILM; Revision: R016; RoHS Status: ROHS_COMPLIANT; Rtd Current: N/A; Rtd Power: 0.063W; Rtd Voltage: 50V; Status: Released; Texas Part Status: Under Review; Type: Resistor; Vendor: VISHAY; Vendor Part Number: CRCW0402100RJNED; Vendor Part Status: Active; WEIGHT: 0.00065g
R21 = RESISTOR: RESISTOR, THICK FILM, 2.2k, -5%/+5%, 0.063W, 50V, -55DEGC/+155DEGC, 0402, SMD; Additional Datasheet URL: N/A; AutoDoc File: https://notefied-dynamic-precision.com/DB/Apps/Desktop/Item/Object.aspx?id=114560; BU Name: TEXAS INSTRUMENTS NORWAY; Budget Currency: EUR; Budget Price: 0.014; Budgetary Price: 0.014 EUR; Client Status: UNDER_REVIEW; Country of Origin: Israel; Datasheet URL: http://www.vishay.com/docs/20035/dcrcwe3.pdf; Datasheet URL 1: http://www.vishay.com/docs/20035/dcrcwe3.pdf; Datasheet URL 2: N/A; Definied Quality: INDUSTRIAL; Esd Level: N/A; Exclusive for Customers: TEXAS INSTRUMENTS NORWAY; Lead Time: 18; LifeCycle Status: ACTIVE; MPN: RESISTOR_0402_2.2k_+/-5%_50V_0.063W_M_+/-200ppm; MPN Status: ACTIVE; MSL: N/A; MTBF: N/A; MTBF Standard: N/A; Manufacturer: MANUFACTURER SELECTION; Mass: 0.00065g; Max Oper Temp: +155DEGC; Max TC: +200PPM/DEGC; Max Tol: +5%; Maximum Operating Temperature: +155DEGC; Maximum Temperature Coefficient: +200PPM/DEGC; Maximum Tolerance: +5%; Min Oper Temp: -55DEGC; Min TC: -200PPM/DEGC; Min Tol: -5%; Minimum Operating Temperature: -55DEGC; Minimum Temperature Coeficient: -200PPM/DEGC; Minimum Tolerance: -5%; Mounting Type: SMD; NOTE Status: PREFERRED; NOTEfied URL: https://notefied-dynamic-precision.com/NOTEfiedWebInterface/part/show?partNumber=01-22487; Notes: Standard item: Duplicate Reason: custom footprint for TEXAS INSTRUMENTS NORWAY.; Old Footprint: RESC1005X40N; PCB Package: 0402; Packing Size: 10000; Packing Type: Tape & Reel; Part Number: 01-22487; Part Type: Resistor|0402|STANDARD; REACH/SVHC Compliance: Compliant; REACH/SVHC Details: SVHC List Version Jun 20, 2016; REACH/SVHC Source: Material Declaration; REACH/SVHC Status: Unaffected; REACH/SVHC_COMPLIANCE: COMPLIANT; REACH/SVHC_DETAILS: SVHC LIST VERSION Jun 20, 2016; REACH/SVHC_SOURCE: MATERIAL DECLARATION; REACH/SVHC_STATUS: UNAFFECTED; ROHS: Exempt; Rated Current: N/A; Rated Power: 0.063W; Rated Voltage: 50V; Resistor Type: THICK FILM; Revision: R013; RoHS Status: ROHS_COMPLIANT; Rtd Current: N/A; Rtd Power: 0.063W; Rtd Voltage: 50V; Status: Released; Texas Part Status: Under Review; Type: Resistor; Vendor: VISHAY; Vendor Part Number: CRCW04022K20JNED; Vendor Part Status: Active; WEIGHT: 0.00065g
SW1 SW2 = SWITCH_1: SWITCH, TACT, RIGHT ANGLE, SPST-NO, 0.05A@12VDC, SMD; Additional Datasheet URL: http://www.dip.com.tw/en/en-product-information/en-switch004/item/2438-mta2; Country of Origin: China,Vietnam; Datasheet URL: http://www.dip.com.tw/en/en-product-information/en-switch004/item/download/2476_096cc44e506e326f4ba9017f6b2ca31d; Mass: N/A; Maximum Operating Temperature: +80DEGC; Minimum Operating Temperature: -30DEGC; Mounting Type: SMD; NOTEfied URL: https://notefied-dynamic-precision.com/NOTEfiedWebInterface/part/show?partNumber=08-00142; Packing Size: 3000; Packing Type: Tape & Reel; Part Number: 08-00142; Part Type: Switch|TACTILE; REACH/SVHC Compliance: Compliant; REACH/SVHC Details: SVHC List Version Dec 17, 2015; REACH/SVHC Source: REACH Declaration; REACH/SVHC Status: Unaffected; ROHS: Compliant; Rated Current: 0.05A; Rated Voltage: 12VDC; Revision: R012; Status: Released; Texas Part Status: Under Review; Type: Switch; Vendor: DIPTRONICS; Vendor Part Number: MTA2-WNC-V-T/R; Vendor Part Status: Active
U2 = IC_FLASH_MX25R8035F_USON8: IC, MEMORY, FLASH, SERIAL, 8Mbit, 1.65V TO 3.6V, USON8, SMD; ALT_SYMBOLS: SON50P300X200X60-9B2L,SON50P300X200X60-9B2M; Additional Datasheet URL: http://www.macronix.com/en-us/products/NOR-Flash/Serial-NOR-Flash/Pages/spec.aspx?p=MX25R8035F&m=Serial%20NOR%20Flash&n=PM2164; AutoDoc File: http://notefied-dynamic-precision.com/DB/Apps/Desktop/Item/Object.aspx?id=104624; Budgetary Price: 0.8598 USD; Country of Origin: Taiwan; Datasheet URL: http://www.macronix.com/Lists/Datasheet/Attachments/7461/MX25R8035F,%20Wide%20Range,%208Mb,%20v1.6.pdf; Datasheet URL 1: N/A; Datasheet URL 2: http://www.macronix.com/Lists/DataSheet/Attachments/2570/MX25R8035F,%20Wide%20Range,%208Mb,%20v0.04.pdf; FPLIST: SON50P300X200X60-9B2N,SON50P300X200X60-9B2L,SON50P300X200X60-9B2M; MPN Status: ACTIVE; Manufacturer: MACRONIX; Mass: N/A; Max Oper Temp: +85DEGC; Maximum Operating Temperature: +85DEGC; Min Oper Temp: -40DEGC; Minimum Operating Temperature: -40DEGC; Mounting Type: SMD; NOTE Status: PREFERRED; NOTEfied URL: https://notefied-dynamic-precision.com/NOTEfiedWebInterface/part/show?partNumber=18-31726; PCB Package: uSON8; Packing Size: 100; Packing Type: Tube; Part Number: 18-31726; Part Type: IC|MEMORY|FLASH|OTHER; REACH/SVHC Compliance: Compliant; REACH/SVHC Details: N/A; REACH/SVHC Source: REACH Declaration & Material Declaration; REACH/SVHC Status: Unaffected; ROHS: Compliant; Rated Voltage: 1.65V TO 3.6V; Revision: R013; RoHS Status: ROHS_COMPLIANT; Rtd Voltage: 1.65V TO 3.6V; Status: Released; Texas Part Status: Under Review; Type: IC; Vendor: MACRONIX; Vendor Part Status: Active
LOGO1 = LABEL_HALL_EFFECT_SENSOR: NON COMPONENT, LOGO, CUSTOM, HALL EFFECT SENSOR; Additional Datasheet URL: N/A; Datasheet URL: N/A; Exclusive for Customers: TEXAS INSTRUMENTS NORWAY; Maximum Operating Temperature: N/A; Minimum Operating Temperature: N/A; Mounting Type: Not Apply; NOTEfied URL: https://notefied-dynamic-precision.com/NOTEfiedWebInterface/part/show?partNumber=19-01166; Notes: Custom Item; Part Number: 19-01166; Part Type: Non Component|LABEL; REACH/SVHC Compliance: Missing Info; REACH/SVHC Details: N/A; REACH/SVHC Source: N/A; REACH/SVHC Status: Missing Info; ROHS: Not Applicable; Revision: R001; Status: Released; Texas Part Status: Under Review; Type: Non Component; Vendor: TEXAS INSTRUMENTS; Vendor Part Status: Active
LOGO2 = LABEL_THERMOSTAT: NON COMPONENT, LOGO, CUSTOM, THERMOSTAT; Additional Datasheet URL: N/A; Datasheet URL: N/A; Exclusive for Customers: TEXAS INSTRUMENTS NORWAY; Maximum Operating Temperature: N/A; Minimum Operating Temperature: N/A; Mounting Type: Not Apply; NOTEfied URL: https://notefied-dynamic-precision.com/NOTEfiedWebInterface/part/show?partNumber=19-01167; Notes: Custom Item; Part Number: 19-01167; Part Type: Non Component|LABEL; REACH/SVHC Compliance: Missing Info; REACH/SVHC Details: N/A; REACH/SVHC Source: N/A; REACH/SVHC Status: Missing Info; ROHS: Not Applicable; Revision: R001; Status: Released; Texas Part Status: Under Review; Type: Non Component; Vendor: TEXAS INSTRUMENTS; Vendor Part Status: Active
LOGO3 = LABEL_ACCELEROMETER: NON COMPONENT, LOGO, CUSTOM, ACCELEROMETER; Additional Datasheet URL: N/A; Datasheet URL: N/A; Exclusive for Customers: TEXAS INSTRUMENTS NORWAY; Maximum Operating Temperature: N/A; Minimum Operating Temperature: N/A; Mounting Type: Not Apply; NOTEfied URL: https://notefied-dynamic-precision.com/NOTEfiedWebInterface/part/show?partNumber=19-01169; Notes: Custom Item; Part Number: 19-01169; Part Type: Non Component|LABEL; REACH/SVHC Compliance: Missing Info; REACH/SVHC Details: N/A; REACH/SVHC Source: N/A; REACH/SVHC Status: Missing Info; ROHS: Not Applicable; Revision: R001; Status: Released; Texas Part Status: Under Review; Type: Non Component; Vendor: TEXAS INSTRUMENTS; Vendor Part Status: Active
LOGO4 = LABEL_LIGHT_SENSOR: NON COMPONENT, LOGO, CUSTOM, LIGHT SENSOR; Additional Datasheet URL: N/A; Datasheet URL: N/A; Exclusive for Customers: TEXAS INSTRUMENTS NORWAY; Maximum Operating Temperature: N/A; Minimum Operating Temperature: N/A; Mounting Type: Not Apply; NOTEfied URL: https://notefied-dynamic-precision.com/NOTEfiedWebInterface/part/show?partNumber=19-01168; Notes: Custom Item; Part Number: 19-01168; Part Type: Non Component|LABEL; REACH/SVHC Compliance: Missing Info; REACH/SVHC Details: N/A; REACH/SVHC Source: N/A; REACH/SVHC Status: Missing Info; ROHS: Not Applicable; Revision: R001; Status: Released; Texas Part Status: Under Review; Type: Non Component; Vendor: TEXAS INSTRUMENTS; Vendor Part Status: Active
U3 = IC_PERIPH_HDC2080_DFN6: IC, TRANSDUCER, LOW POWER HUMIDITY AND TEMPERATURE DIGITAL SENSOR, 1.62V TO 3.6V, WSON6-EP, SMD; ALT_SYMBOLS: SON100P300X300X80-7B2L,SON100P300X300X80-7B2M; Additional Datasheet URL: N/A; Datasheet URL: http://www.ti.com/lit/ds/symlink/hdc2080.pdf; Mass: 0.0259g; Maximum Operating Temperature: +85DEGC; Minimum Operating Temperature: -40DEGC; Mounting Type: SMD; NOTEfied URL: https://notefied-dynamic-precision.com/NOTEfiedWebInterface/part/show?partNumber=18-33414; PCB Package: WSON6-EP; Packing Size: 3000; Packing Type: Tape & Reel; Part Number: 18-33414; Part Type: IC|TRANSDUCER|HUMIDITY; REACH/SVHC Compliance: Compliant; REACH/SVHC Details: SVHC List Version Jan 15, 2019; REACH/SVHC Source: REACH Declaration; REACH/SVHC Status: Unaffected; ROHS: Compliant; Rated Voltage: 1.62V TO 3.6V; Revision: R018; Status: Released; Texas Part Status: Under Review; Type: IC; Vendor: TEXAS INSTRUMENTS; Vendor Part Number: HDC2080DMBR; Vendor Part Status: Active
U4 = IC_PERIPH_DRV5055_SOT23-3: IC, ULTRA-LOW-POWER, HALL EFFECT SENSOR, DIGITAL, SOT23-3, SMD; ALT_SYMBOLS: SOT95P237X112-3A2L,SOT95P237X112-3A2M; Additional Datasheet URL: http://www.ti.com/lit/ml/mpds108d/mpds108d.pdf; Budgetary Price: 0.58 USD; Datasheet URL: http://www.ti.com/lit/ds/symlink/drv5055.pdf; Lead Time: 6; Mass: 0.0096g; Maximum Operating Temperature: +125DEGC; Minimum Operating Temperature: -40DEGC; Mounting Type: SMD; NOTEfied URL: https://notefied-dynamic-precision.com/NOTEfiedWebInterface/part/show?partNumber=18-35025; PCB Package: SOT23-3; Packing Size: 250; Packing Type: Tape & Reel; Part Number: 18-35025; Part Type: IC|TRANSDUCER|MAGNETIC FIELD; REACH/SVHC Compliance: Compliant; REACH/SVHC Details: SVHC List Version Jun 27, 2018; REACH/SVHC Source: REACH Declaration; REACH/SVHC Status: Unaffected; ROHS: Compliant; Rated Voltage: 1.65V TO 5.5V; Revision: R006; Status: Released; Texas Part Status: Under Review; Type: IC; Vendor: TEXAS INSTRUMENTS; Vendor Part Number: DRV5032FBDBZR; Vendor Part Status: Active
U5 = IC_ACC_ADXL362_LGA16: IC, TRANSDUCER, MICROPOWER, 3-AXIS DIGITAL OUTPUT MEMS ACCELEROMETER, 1.6V TO 3.5V, LGA16, SMD; Additional Datasheet URL: https://www.analog.com/media/en/package-pcb-resources/package/pkg_pdf/lgacc/cc_16_4.pdf; Budgetary Price: 4.37 USD; Country of Origin: South Korea; Datasheet URL: https://www.analog.com/media/en/technical-documentation/data-sheets/ADXL362.pdf; Lead Time: 6; Mass: 0.0194g; Maximum Operating Temperature: +85DEGC; Minimum Operating Temperature: -40DEGC; Mounting Type: SMD; NOTEfied URL: https://notefied-dynamic-precision.com/NOTEfiedWebInterface/part/show?partNumber=18-33965; PCB Package: LGA16; Packing Size: 250; Packing Type: Tape & Reel; Part Number: 18-33965; Part Type: IC|TRANSDUCER|ACCELERATION; REACH/SVHC Compliance: Compliant; REACH/SVHC Details: SVHC List Version Jul 07, 2017; REACH/SVHC Source: Material Declaration; REACH/SVHC Status: Unaffected; ROHS: Exempt; Rated Voltage: 1.6V TO 3.5V; Revision: R014; Status: Released; Texas Part Status: Under Review; Type: IC; Vendor: ANALOG DEVICES; Vendor Part Number: ADXL362BCCZ-R2; Vendor Part Status: Active
U6 = IC_PERIPH_OPT3001_SON6: IC, TRANSDUCER, AMBIENT LIGHT SENSOR, OPT3001, 1.6V TO 3.6V, SON6, SMD; ALT_SYMBOLS: SON65P200X200X65-7L,SON65P200X200X65-7M; Additional Datasheet URL: http://www.ti.com/litv/pdf/mpds564b; Budgetary Price: 0.99 USD; Country of Origin: Missing Info; Datasheet URL: http://www.ti.com/lit/ds/symlink/opt3001.pdf; Exclusive for Customers: TEXAS INSTRUMENTS NORWAY; Mass: 0.0084g; Maximum Operating Temperature: +85DEGC; Minimum Operating Temperature: -40DEGC; Mounting Type: SMD; NOTEfied URL: https://notefied-dynamic-precision.com/NOTEfiedWebInterface/part/show?partNumber=18-28621; Notes: Custom Item; PCB Package: SON6; Packing Size: 3000; Packing Type: Tape & Reel; Part Number: 18-28621; Part Type: IC|TRANSDUCER|LIGHT; REACH/SVHC Compliance: Compliant; REACH/SVHC Details: SVHC List Version Jan 12, 2017; REACH/SVHC Source: REACH Declaration; REACH/SVHC Status: Unaffected; ROHS: Compliant; Rated Voltage: 1.6V TO 3.6V; Revision: R018; Status: Released; Texas Part Status: Under Review; Type: IC; Vendor: TEXAS INSTRUMENTS; Vendor Part Number: OPT3001DNPR; Vendor Part Status: Active

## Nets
GND: C20.2 C21.2 C22.2 C23.2 C24.2 C25.2 J2.4 J3.2 P2.3 P2.5 P2.9 P3.5 Q1.2(EMITTER) Q2.2(EMITTER) Q3.2(EMITTER) R12.1 R14.1 R20.1 R37.2 SW1.1 SW2.1 U2.4(GND) U2.9(EGP) U3.2(GND) U4.3(GND) U5.3(RSVD) U5.5(RSVD) U5.10(RSVD) U5.12(GND) U5.13(GND) U5.16(GND) U6.3(GND) U6.7(EGP/GND) ; also on sheet 1 4
VDD: CR1.4(4+) J2.1 P2.1 P3.1 R15.2 R16.2 R21.2 R22.2 R23.2 R24.1 R25.2 R26.2 R29.2 R30.2 ; also on sheet 1 4
ACC_INT: J2.16 R31.1 U1.43(DIO_30)
ACC_nCS: J3.6 U1.17(DIO_11) U5.8(nCS)
BP_RESET: J3.11 R6.2
DIO3: J3.4 U1.8(DIO_3)
DIO6_RLED: J3.3 R19.2 U1.11(DIO_6)
DIO7_GLED: J3.1 R13.2 U1.12(DIO_7)
DIO12_RXD: J2.5 U1.18(DIO_12)
DIO13_TXD: J2.7 U1.19(DIO_13)
DIO14_BTN2: J3.18 R18.2 U1.20(DIO_14)
DIO15_BTN1: J3.16 R17.2 U1.21(DIO_15)
DIO16_TDO: P2.6 R4.2 U1.26(DIO_16)
DIO17_TDI: P2.8 R5.2 U1.27(DIO_17)
DIO19_CTS: J3.7 U1.29(DIO_19)
DIO20_FLASH_CS: J3.5 R21.1 U1.30(DIO_20) U2.1(nCS)
DIO21_BLED: J2.15 R11.2 U1.31(DIO_21)
DIO22: J2.9 U1.32(DIO_22)
DIO24_Analog: J2.11 U1.37(DIO_24)
DIO26_Analog: J2.8 U1.39(DIO_26)
DIO28_Analog: J2.12 U1.41(DIO_28)
DIO29_Analog: J2.14 U1.42(DIO_29)
HDC_INT: J2.6 R27.1 U1.38(DIO_25)
LP_RESET: J3.10 R7.2
OPT_INT: J2.10 R32.1 U1.40(DIO_27)
WMCU_MISO: J3.14 U1.14(DIO_8) U2.2(SO/SIO1) U5.7(MISO)
WMCU_MOSI: J3.12 U1.15(DIO_9) U2.5(SI/SIO0) U5.6(MOSI)
WMCU_REED: J2.3 R28.1 U1.36(DIO_23)
WMCU_RESET: P2.10 P3.4 R6.1 R7.1 ; also on sheet 1
WMCU_SCL: J2.17 R15.1 U1.9(DIO_4) U3.6(SCL) U6.4(nCLK)
WMCU_SCLK: J2.13 U1.16(DIO_10) U2.6(SCLK) U5.4(SCLK)
WMCU_SDA: J2.19 R16.1 U1.10(DIO_5) U3.1(SDA) U6.6(DATA)
WMCU_SWO: J3.9 U1.28(DIO_18)
WMCU_TCK: P2.4 P3.3 R3.2 ; also on sheet 1
WMCU_TMS: P2.2 P3.2 R2.2 ; also on sheet 1
N1017630: C20.1 R24.2 U2.8(VCC)
N1176544: J3.13 R2.1
N1176548: J3.15 R3.1
N1176568: J3.17 R4.1
N1177007: J3.19 R5.1
N1409884: R23.1 U2.3(nWP/SIO2)
N1409917: R22.1 U2.7(nRST/SIO3)
N2699398: C21.1 R25.1 U3.3(ADDR) U3.5(VDD)
N2700735: C22.1 R26.1 U4.1(VCC)
N2701534: R36.1 R37.1 U6.2(ADDR)
N2701865: C25.1 R29.1 R36.2 U6.1(VDD)
N2717734: R31.2 U5.11(INT1)
N2718017: R32.2 U6.5(nINT)
N2720505: R27.2 U3.4(DRDY/INT)
N2766833: Q1.1(BASE) R11.1 R12.2
N2766949: Q2.3(COLLECTOR) R10.1
N2766991: Q2.1(BASE) R13.1 R14.2
N2767546: Q3.3(COLLECTOR) R9.1
N2767588: Q3.1(BASE) R19.1 R20.2
N2769696: Q1.3(COLLECTOR) R8.1
N2792373: R17.1 SW1.2
N2796131: R18.1 SW2.2
N3041603: CR1.2(2G-) R10.2
N3041676: CR1.1(1R-) R9.2
N3041751: CR1.3(3B-) R8.2
N3043961: R28.2 U4.2(OUT)
N3297320: C23.1 C24.1 R30.1 U5.1(VDDI/O) U5.14(VS)

Not connected (* = marked no-connect by the designer): J2 2* 18* 20*; J3 8* 20*; P2 7*; U3 7(EGP)*; U5 2(NC)* 9(INT2)* 15(NC)*

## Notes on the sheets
sheet 2
- BoosterPack Headers and Peripherals
- 1
- 21
- 40
- 20
- 2
- 22
- 39
- 19
- 3
- 23
- 38
- 18
- 4
- 24
- 37
- 17
- 5
- 6
- 25
- 26
- 35
- 36
- 15
- 16
- 7
- 27
- 34
- 14
- 8
- 28
- 33
- 13
- 9
- 29
- 32
- 12
- 10
- 30
- 31
- 11
- Wireless MCU IO block
- JTAG Connection
- MCU071
- External flash
sheet 3
- SENSORS
- Humidity and Temperature Sensor
- Hall Effect Sensor
- Accelerometer
- Ambient Light Sensor
- MCU071
